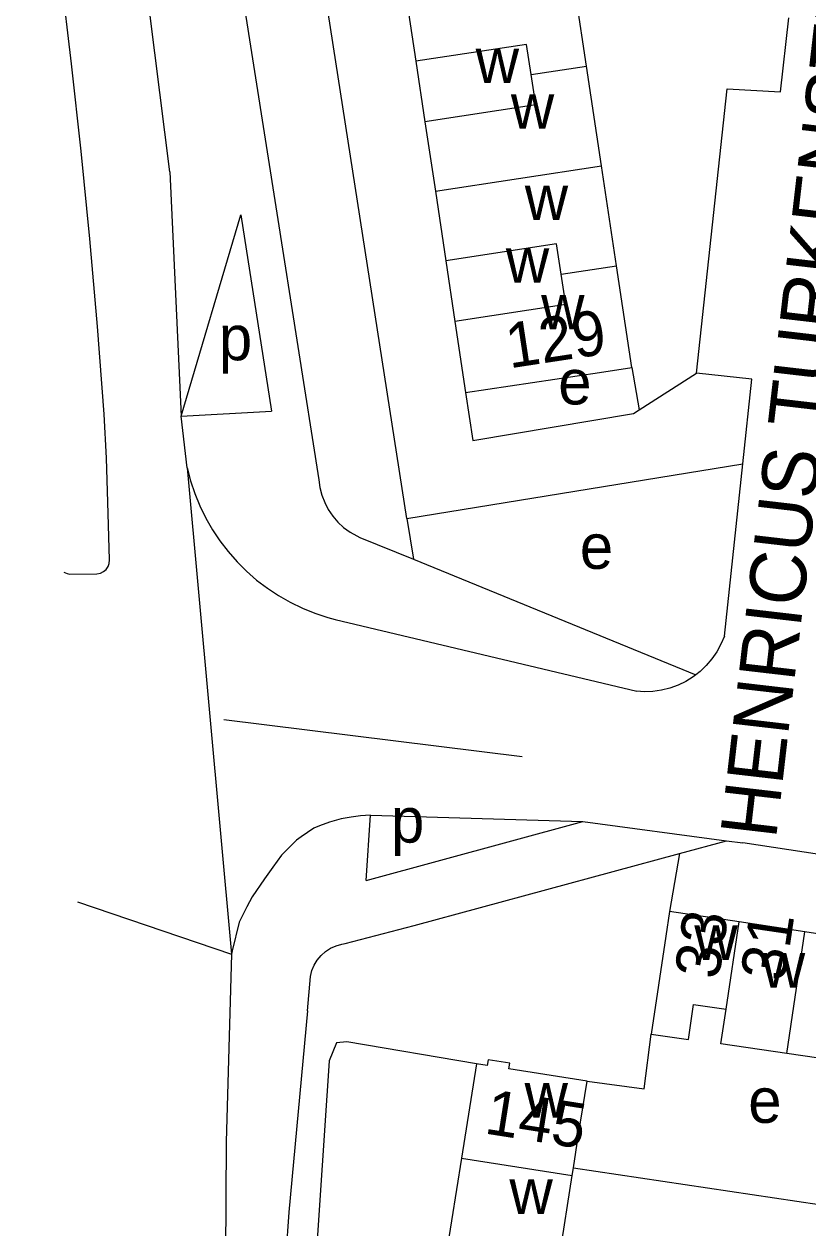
# Model space of a CAD drawing. Extents: x 163012 to 165277, y 382513 to 383987.
# Drawn here: x 163176.2 to 163246.1, y 383224 to 383331.4 of the extents above; entities that cross this region are included whole.
import ezdxf

# ---------------------------------------------------------------- set-up
doc = ezdxf.new("R2010")
doc.units = 0
for name, color, linetype in [('BLT_Basislijn', 7, 'Continuous'), ('BLT_Bebouwing', 7, 'Continuous'), ('BLT_Centroide', 7, 'Continuous'), ('BLT_Huisnummer', 7, 'Continuous'), ('BLT_Huisnummer_ tussenligend', 7, 'Continuous'), ('BLT_Huisnummer_reeks', 7, 'Continuous'), ('BLT_Onderverdeling_panden', 7, 'Continuous'), ('BLT_Straatnaam', 7, 'Continuous'), ('BLT_Vlakafsluiter', 7, 'Continuous')]:
    doc.layers.add(name, color=color, linetype=linetype)

msp = doc.modelspace()

# ---------------------------------------------------------------- linework, layer by layer
at = {"layer": 'BLT_Basislijn'}
for p, q in [((163210.36, 383287.25), (163192.89, 383399.7)), ((163192.66, 383353.29), (163198.76, 383314.48)), ((163198.76, 383314.48), (163202.5, 383290.7)), ((163195.54, 383314.33), (163198.29, 383296.84)), ((163230.44, 383300.72), (163231.08, 383296.94)), ((163231.08, 383296.94), (163236.19, 383300.23)), ((163190.23, 383296.38), (163198.29, 383296.84)), ((163190.77, 383291.78), (163190.23, 383296.38)), ((163210.36, 383287.25), (163240.33, 383292.14)), ((163238.68, 383276.75), (163240.33, 383292.14)), ((163183.83, 383283.56), (163183.69, 383288.7)), ((163210.36, 383287.25), (163210.94, 383283.62)), ((163206.16, 383285.57), (163210.94, 383283.62)), ((163210.94, 383283.62), (163236.14, 383273.31)), ((163180.29, 383282.3), (163182.72, 383282.32)), ((163203.96, 383278.25), (163230.88, 383271.84)), ((163194.04, 383269.32), (163220.65, 383266.03)), ((163206.73, 383254.97), (163207.13, 383260.79)), ((163206.73, 383254.97), (163226.05, 383260.21)), ((163226.05, 383260.21), (163238.88, 383258.51)), ((163234.67, 383257.37), (163238.88, 383258.51)), ((163238.88, 383258.51), (163240.34, 383258.32)), ((163281.2, 383252.08), (163240.34, 383258.32)), ((163211.01, 383250.95), (163234.67, 383257.37)), ((163234.67, 383257.37), (163233.79, 383252.18)), ((163204.86, 383249.33), (163211.01, 383250.95)), ((163194.73, 383248.4), (163194.24, 383231.65)), ((163201.49, 383243.33), (163201.75, 383246.4)), ((163201.49, 383243.33), (163199.84, 383225.38)), ((163194.24, 383231.65), (163194.15, 383213.88)), ((163199.84, 383225.38), (163198.95, 383213.08))]:
    msp.add_line(p, q, dxfattribs=at)
for points in [[(163189.23, 383318.17), (163186.12, 383342.73), (163183.37, 383360.88)], [(163183.37, 383296.55), (163182.76, 383304.38), (163182.07, 383312.2), (163181.3, 383320.01), (163180.45, 383327.82), (163179.52, 383335.62), (163178.51, 383343.41), (163177.42, 383351.18), (163176.25, 383358.95), (163176.22, 383359.17)], [(163236.19, 383300.23), (163238.93, 383325.59), (163243.7, 383325.32), (163244.44, 383331.91)], [(163190.23, 383296.38), (163195.54, 383314.33)], [(163240.33, 383292.14), (163241.14, 383299.68), (163236.19, 383300.23)], [(163215.6, 383298.48), (163216.24, 383294.2), (163230.58, 383296.62), (163231.08, 383296.94)], [(163183.69, 383288.7), (163183.56, 383292.64), (163183.37, 383296.55)], [(163190.77, 383291.78), (163191.07, 383290.62), (163191.45, 383289.48), (163191.9, 383288.37), (163192.43, 383287.29), (163193.02, 383286.25), (163193.69, 383285.25), (163194.42, 383284.3), (163195.21, 383283.4), (163196.06, 383282.55), (163196.96, 383281.76), (163197.92, 383281.03), (163198.92, 383280.37), (163199.96, 383279.78), (163201.04, 383279.25), (163202.15, 383278.8), (163203.3, 383278.43), (163203.96, 383278.25)], [(163202.5, 383290.7), (163202.6, 383290.01), (163202.77, 383289.33), (163203.03, 383288.67), (163203.35, 383288.05), (163203.75, 383287.47), (163204.21, 383286.93), (163204.72, 383286.46), (163205.29, 383286.04), (163205.9, 383285.7), (163206.16, 383285.57)], [(163182.72, 383282.32), (163183.02, 383282.38), (163183.3, 383282.51), (163183.53, 383282.71), (163183.71, 383282.96), (163183.81, 383283.25), (163183.83, 383283.56)], [(163179.77, 383282.46), (163180.06, 383282.34), (163180.29, 383282.3)], [(163238.68, 383276.75), (163238.38, 383276.03), (163238.01, 383275.36), (163237.57, 383274.72), (163237.07, 383274.13), (163236.51, 383273.6), (163236.14, 383273.31)], [(163236.14, 383273.31), (163235.9, 383273.13), (163235.24, 383272.72), (163234.55, 383272.38), (163233.82, 383272.12), (163233.07, 383271.93), (163232.31, 383271.83), (163231.54, 383271.8), (163230.88, 383271.84)], [(163207.13, 383260.79), (163206.22, 383260.73), (163205.38, 383260.62), (163204.5, 383260.45), (163203.45, 383260.16), (163202.57, 383259.85), (163202.06, 383259.62), (163200.94, 383258.86), (163200.53, 383258.57), (163199.17, 383257.21), (163198.41, 383256.16), (163197.65, 383255.1), (163196.55, 383253.51), (163196.1, 383252.6), (163195.41, 383251.23), (163194.77, 383248.67), (163194.73, 383248.4)], [(163207.13, 383260.79), (163226.05, 383260.21)], [(163201.75, 383246.4), (163201.88, 383246.92), (163202.09, 383247.41), (163202.36, 383247.86), (163202.71, 383248.27), (163203.1, 383248.63), (163203.55, 383248.92), (163204.04, 383249.14), (163204.55, 383249.28), (163204.86, 383249.33)], [(163216.56, 383238.6), (163205.02, 383240.56), (163204.07, 383240.49), (163203.42, 383238.87), (163200.13, 383189.6)], [(163226.43, 383237.05), (163231.52, 383236.37), (163232.16, 383241.26)], [(163225.21, 383229.34), (163251.12, 383225.45), (163251.88, 383225.34)]]:
    msp.add_lwpolyline(points, dxfattribs=at)
at = {"layer": 'BLT_Bebouwing'}
for p, q in [((163226.38, 383327.6), (163225.04, 383336.48)), ((163210.23, 383334.25), (163211.16, 383328.05)), ((163211.16, 383328.05), (163211.97, 383322.65)), ((163227.73, 383318.7), (163226.38, 383327.6)), ((163211.97, 383322.65), (163212.9, 383316.45)), ((163229.07, 383309.8), (163227.73, 383318.7)), ((163212.9, 383316.45), (163213.84, 383310.25)), ((163213.84, 383310.25), (163214.65, 383304.84)), ((163230.44, 383300.72), (163229.07, 383309.8)), ((163214.65, 383304.84), (163215.6, 383298.48)), ((163240, 383251.26), (163233.79, 383252.18)), ((163245.86, 383250.39), (163240, 383251.26)), ((163250.11, 383238.67), (163244.24, 383239.53)), ((163216.56, 383238.6), (163215.24, 383230.2)), ((163215.24, 383230.2), (163213.91, 383221.81)), ((163223.78, 383220.25), (163225.11, 383228.65)), ((163225.11, 383228.65), (163225.21, 383229.34))]:
    msp.add_line(p, q, dxfattribs=at)
for points in [[(163215.6, 383298.48), (163227.54, 383300.29), (163230.44, 383300.72)], [(163233.79, 383252.18), (163233.46, 383250), (163232.16, 383241.26)], [(163251.73, 383249.52), (163248.36, 383250), (163245.86, 383250.39)], [(163232.16, 383241.26), (163235.47, 383240.78), (163235.93, 383243.91), (163238.84, 383243.49)], [(163244.24, 383239.53), (163238.38, 383240.4), (163238.84, 383243.49)], [(163226.43, 383237.05), (163219.45, 383238.15), (163219.53, 383238.65), (163217.61, 383238.95), (163217.53, 383238.45), (163216.56, 383238.6)], [(163225.21, 383229.34), (163225.65, 383232.11), (163226.43, 383237.05)]]:
    msp.add_lwpolyline(points, dxfattribs=at)
at = {"layer": 'BLT_Onderverdeling_panden'}
for p, q in [((163221.03, 383329.55), (163211.16, 383328.05)), ((163221.44, 383326.85), (163221.03, 383329.55)), ((163221.44, 383326.85), (163226.38, 383327.6)), ((163221.85, 383324.15), (163221.44, 383326.85)), ((163221.85, 383324.15), (163211.97, 383322.65)), ((163212.9, 383316.45), (163227.73, 383318.7)), ((163223.72, 383311.75), (163213.84, 383310.25)), ((163224.13, 383309.05), (163223.72, 383311.75)), ((163224.13, 383309.05), (163229.07, 383309.8)), ((163224.54, 383306.35), (163224.13, 383309.05)), ((163224.54, 383306.35), (163214.65, 383304.84)), ((163238.84, 383243.49), (163240, 383251.26)), ((163244.24, 383239.53), (163245.86, 383250.39)), ((163215.24, 383230.2), (163225.11, 383228.65))]:
    msp.add_line(p, q, dxfattribs=at)
at = {"layer": 'BLT_Vlakafsluiter'}
for p, q in [((163189.23, 383318.17), (163190.23, 383296.38)), ((163190.77, 383291.78), (163194.73, 383248.4)), ((163180.99, 383253.05), (163194.73, 383248.4))]:
    msp.add_line(p, q, dxfattribs=at)

# ---------------------------------------------------------------- texts
at = {"layer": 'BLT_Centroide'}
for s, p in [('w', (163216.5, 383326.09)), ('w', (163219.64, 383322.03)), ('w', (163220.88, 383313.88)), ('w', (163219.19, 383308.28)), ('w', (163222.34, 383304.12)), ('p', (163193.59, 383301.37)), ('e', (163223.86, 383297.43)), ('e', (163225.79, 383282.76)), ('p', (163208.94, 383258.34)), ('w', (163236, 383247.88)), ('w', (163242.02, 383245.41)), ('w', (163220.86, 383233.81)), ('e', (163240.81, 383233.34)), ('w', (163219.51, 383225.22))]:
    msp.add_text(s, height=4, dxfattribs=at).set_placement(p)
at = {"layer": 'BLT_Huisnummer'}
msp.add_text('33', height=4, rotation=81.591, dxfattribs=at).set_placement((163238.17, 383246.05))
at = {"layer": 'BLT_Huisnummer_ tussenligend'}
msp.add_text('31', height=4, rotation=81.589, dxfattribs=at).set_placement((163244.05, 383245.87))
at = {"layer": 'BLT_Huisnummer_reeks'}
for s, rotation, p in [('129', 8.6513, (163219.51, 383300.64)), ('145', 351.028, (163217.18, 383232.41))]:
    msp.add_text(s, height=4, rotation=rotation, dxfattribs=at).set_placement(p)
at = {"layer": 'BLT_Straatnaam'}
msp.add_text('HENRICUS TURKENSTRAAT', height=5, rotation=83.382, dxfattribs=at).set_placement((163243.28, 383258.59))

doc.saveas('drawing.dxf')
